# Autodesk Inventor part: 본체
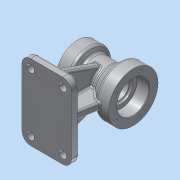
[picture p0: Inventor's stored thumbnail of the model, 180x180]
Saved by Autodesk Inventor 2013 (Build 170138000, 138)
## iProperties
Created: 2015-08
Part Number: 본체
Material: 알루미늄 6061
Document SubType Name: Modeling
Designer: Administrator
Density: 2.71 g/cm^3
Mass: 1062.79 g
Surface Area: 749.652 cm^2
Volume: 392.172 cm^3
Author: Administrator
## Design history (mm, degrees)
sketch "스케치1"
  geometry: L1 (0, 0)-(90, 0); L2 (0, 0)-(0, 35); L3 (25.196, 26)-(53.315, 26); L4 (53.315, 26)-(70, 40); L5 (70, 40)-(90, 40); L6 (90, 40)-(90, 0); L7 (0, 35)-(20, 35); L8 (20, 35)-(25.196, 26); 1 further point
  constraints: 16 end point, 4 horizontal, 2 vertical, 1 midpoint
  dimensions: "d6" = 90 distance of L1.start L1.end; "d7" = 40 deg angle of L4 L3; "d8" = 60 deg angle of L3 L8; "d9" = 20 distance of L4.end L5.end; "d10" = 20 distance of L2.end L7.end; "d11" = 70 diameter of L7 L1; "d12" = 52 diameter of L3 L1; "d13" = 80 diameter of L5 L1
revolve "회전1" sketch "스케치1" stored, may be unused: angle "d14" = 90 deg
sketch "스케치2"
  geometry: L1 (0, -78)-(80, -78); L2 (80, -78)-(80, -90); L3 (80, -90)-(0, -90); L4 (0, -90)-(0, -78); L5 (0, -35)-(0, 35) reference; L6 (0, 35)-(20, 35) reference; L7 (20, 35)-(25.196, 26) reference; L8 (25.196, 26)-(53.315, 26) reference; L9 (53.315, 26)-(70, 40) reference; L10 (70, 40)-(90, 40) reference; L11 (90, 40)-(90, -40) reference; L12 (90, -40)-(70, -40) reference; L13 (70, -40)-(53.315, -26) reference; L14 (53.315, -26)-(25.196, -26) reference; L15 (25.196, -26)-(20, -35) reference; L16 (20, -35)-(0, -35) reference; 1 further point
  constraints: 8 end point, 2 parallel, 1 horizontal, 1 perpendicular, 1 vertical alignment
  dimensions: "d15" = 90 distance from line of L3 point (0, 0); "d16" = 12 distance of L1.end L2.end; "d17" = 80 distance of L2.end L3.end
extrude "돌출1" join sketch "스케치2" stored distance "d18" = 122; taper "d19" = 0 deg
node "작업 평면1"
sketch "스케치3"
  geometry: L1 (122, 12)-(122, 0) reference; L2 (122, 0)-(0, 0) reference; L3 (0, 0)-(0, 12) reference; L4 (0, 12)-(122, 12) reference; L5 (122, 12)-(122, 0) reference; L6 (122, 0)-(0, 0) reference; L7 (0, 0)-(0, 12) reference; L8 (0, 12)-(122, 12) reference; L9 (10, 12)-(35.909, 83.185); L10 (86.091, 83.185)-(112, 12); C1 r 26 at (61, 90) reference; A1 r 26 centre (61, 90) between (35.909, 83.185) and (86.091, 83.185) reference; 1 further point
  constraints: 4 end point, 2 point on circle, 2 point on line
  dimensions: "d21" = 70 deg angle of L4 L10; "d22" = 70 deg angle of L4 L9; "d23" = 10 distance from line of L10.end L1; "d24" = 10 distance of L9.start L3.end
extrude "돌출2" join sketch "스케치3" stored distance "d25" = 12; taper "d26" = 0 deg
sketch "스케치4"
  geometry: L1 (0, -35)-(0, 35) reference; L2 (0, 35)-(20, 35) reference; L3 (20, 35)-(25.196, 26) reference; L4 (25.196, 26)-(53.315, 26) reference; L5 (53.315, 26)-(70, 40) reference; L6 (70, 40)-(90, 40) reference; L7 (90, 40)-(90, -40) reference; L8 (90, -40)-(70, -40) reference; L9 (70, -40)-(53.315, -26) reference; L10 (53.315, -26)-(46, -26) reference; L11 (46, -26)-(46, -78) reference; L12 (46, -78)-(80, -78) reference; L13 (80, -78)-(80, -90) reference; L14 (80, -90)-(0, -90) reference; L15 (0, -90)-(0, -78) reference; L16 (0, -78)-(34, -78) reference; L17 (34, -78)-(34, -26) reference; L18 (34, -26)-(25.196, -26) reference; L19 (25.196, -26)-(20, -35) reference; L20 (20, -35)-(0, -35) reference; L21 (70, -78)-(76.7, -40); L22 (10, -35)-(10, -78); 1 further point
  constraints: 4 end point, 3 point on line, 1 midpoint, 1 vertical
  dimensions: "d27" = 10 distance from line of L21.start L13; "d28" = 80 deg angle of L21 L12; "d29" = 10 distance between parallel lines of L22 L15
  node "절단 모서리 투영4"
feature "리브1" dims "d30" = 1, "d31" = 12, "d32" = 0, "d33" = 0, "d34" = 1, "d35" = 1
feature "리브2" dims "d36" = 1, "d37" = 12, "d38" = 0, "d39" = 0, "d40" = 1, "d41" = 1
fillet "모깎기1" dims "d42" = 14
fillet "모깎기2" dims "d43" = 3
sketch "스케치5"
  geometry: C1 r 6 at (0, -11); C2 r 6 at (52, -11); C3 r 6 at (52, -105); C4 r 6 at (0, -105); A1 r 11 centre (52, -11) between (63, -11) and (52, 0) reference; A2 r 11 centre (0, -11) between (0, 0) and (-11, -11) reference; A3 r 11 centre (0, -105) between (-11, -105) and (0, -116) reference; A4 r 11 centre (52, -105) between (52, -116) and (63, -105) reference; 1 further point
  constraints: 4 centre point, 4 coincident
  dimensions: "d44" = 12 diameter of C1; "d45" = 12 diameter of C2; "d46" = 12 diameter of C3; "d47" = 12 diameter of C4
extrude "돌출3" cut sketch "스케치5" stored distance "d48" = 12; taper "d49" = 0 deg
fillet "모깎기3" dims "d50" = 5
fillet "모깎기4" dims "d51" = 3
fillet "모깎기5" dims "d52" = 3
fillet "모깎기6" dims "d53" = 3
fillet "모깎기7" dims "d54" = 3
sketch "스케치6"
  geometry: C1 r 40 at (0, 0) reference; C2 r 26 at (0, 0)
  constraints: 1 centre point, 1 coincident
  dimensions: "d55" = 52 diameter of C2
extrude "돌출4" cut sketch "스케치6" distance "d56" = 20; taper "d57" = 0 deg
sketch "스케치7"
  geometry: C1 r 26 at (0, 0) reference; C2 r 19 at (0, 0)
  constraints: 1 centre point, 1 coincident
  dimensions: "d58" = 38 diameter of C2
extrude "돌출5" cut sketch "스케치7" distance "d59" = 3; taper "d60" = 0 deg
sketch "스케치8"
  geometry: C1 r 35 at (0, 0) reference; C2 r 20 at (0, 0)
  constraints: 1 centre point, 1 coincident
  dimensions: "d61" = 40 diameter of C2
extrude "돌출6" cut sketch "스케치8" distance "d62" = 17; taper "d63" = 0 deg
fillet "모깎기8" dims "d64" = 3
sketch "스케치9"
  geometry: C1 r 16 at (0, 0) reference; C2 r 16 at (0, 0)
  constraints: 1 centre point, 1 coincident
  dimensions: "d65" = 32 diameter of C2
extrude "돌출7" cut sketch "스케치9" stored distance "d66" = 17; taper "d67" = 0 deg
chamfer "모따기1" distance "d68" = 1; stored, may be unused: second distance "d69" = 2, angle "d70" = 45 deg
fillet "모깎기9" dims "d71" = 0.3
sketch "스케치10"
  geometry: C1 r 40 at (0, 0) reference; 1 further point
  constraints: 1 vertical alignment
  dimensions: "d72" = 33 distance of point (0, 33) C1.centre
hole "구멍1" sketch "스케치10" at (0, 33) diameter "d73" = 3.242; stored, may be unused: countersink angle "d77" = 90 deg, drill point angle "d79" = 118 deg; dims "d74" = 10, "d75" = 4, "d76" = 2, "d78" = 13
sketch "스케치11"
  geometry: C1 r 35 at (0, 0) reference; 1 further point
  constraints: 1 vertical alignment
  dimensions: "d83" = 27 distance of C1.centre point (0, 27)
hole "구멍2" sketch "스케치11" at (0, 27) diameter "d84" = 3.242; stored, may be unused: countersink angle "d88" = 90 deg, drill point angle "d90" = 118 deg; dims "d85" = 10, "d86" = 4, "d87" = 2, "d89" = 13
sketch "스케치12"
  geometry: L1 (14, 0)-(108, 0) reference; L2 (79, 30)-(79, 36); L3 (91, 36)-(91, 30); A1 r 29 centre (61, 90) between (70, 62.432) and (85.856, 75.06) reference; A2 r 6 centre (85, 30) between (79, 30) and (91, 30); A3 r 6 centre (85, 36) between (91, 36) and (79, 36)
  constraints: 4 end point, 4 point on circle, 4 tangent, 2 centre point, 1 equal radius, 1 vertical alignment
  dimensions: "d94" = 30 distance from line of L1 A2.centre; "d95" = 24 horizontal distance of A2.centre A1.centre; "d96" = 12 diameter of A3; "d97" = 18 dimension on A2 A3
extrude "돌출8" cut sketch "스케치12" stored distance "d98" = 17; taper "d99" = 0 deg
sketch "스케치13"
  geometry: L1 (53, -3)-(1, -3) reference; L2 (-3, 37.119)-(-3, 0) reference; 2 further points
  constraints: 1 other
  dimensions: "d100" = 24 distance from line of point (13, 21) L1; "d101" = 16 distance from line of point (13, 21) L2
feature "엠보싱1" sketch "스케치13" dims "d102" = 0.5, "d103" = 0
node "솔리드1"
pattern_circular "원형 패턴1" dims angle "d81" = 360 deg
pattern_circular "원형 패턴2" dims angle "d92" = 360 deg
mirror "대칭1"
node "절단 모서리 투영1"
node "절단 모서리 투영2"
node "절단 모서리 투영3"
